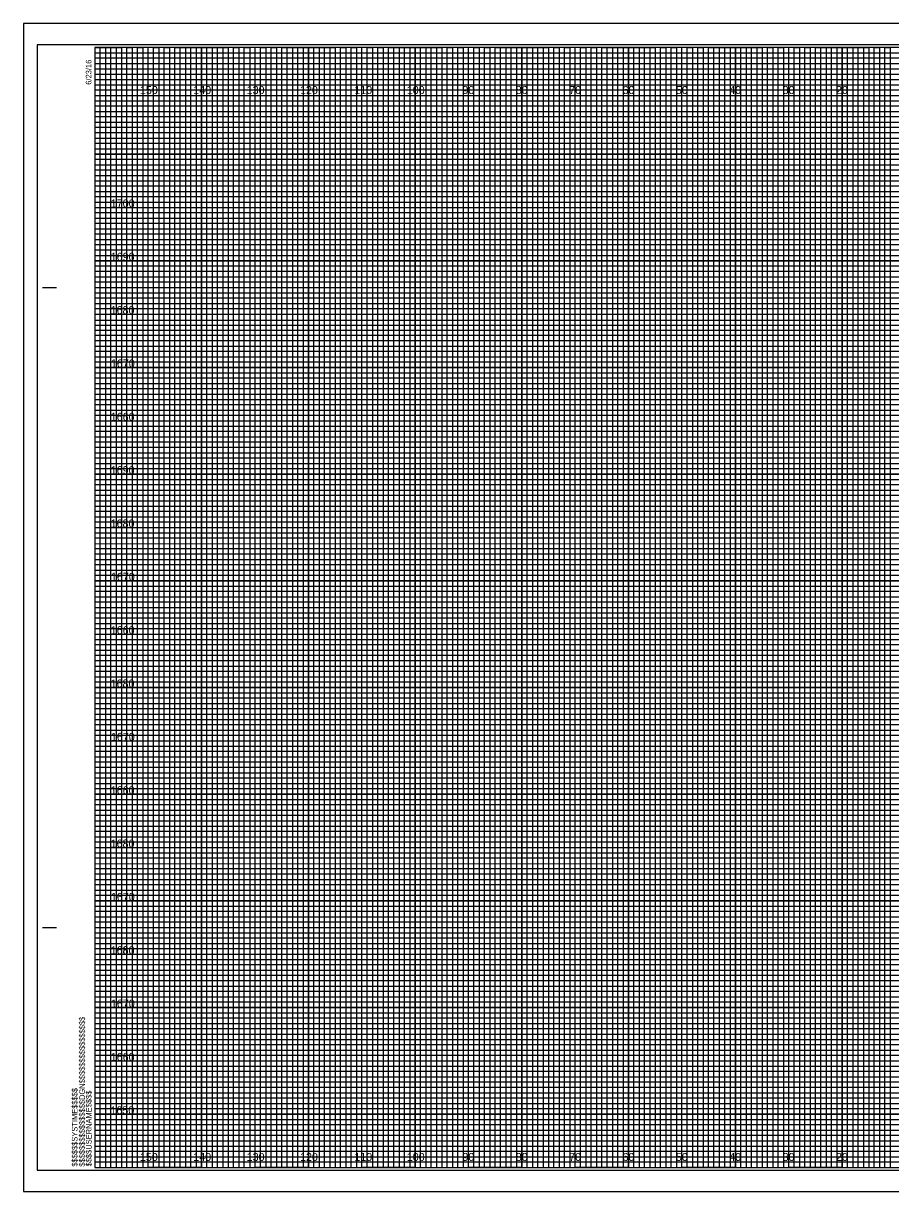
# Model space of a CAD drawing. Extents: x -13 to 323, y -5 to 434.
# Drawn here: x -13.4 to 149.1, y -4.5 to 214.5 of the extents above; entities that cross this region are included whole.
import ezdxf

# ---------------------------------------------------------------- set-up
doc = ezdxf.new("R2010")
doc.units = 0
for name, color, linetype in [('Prop Horizontal Alignment', 7, 'Continuous'), ('Raster_Level_0', 7, 'Continuous'), ('Sheet Cross Section CELL', 7, 'Continuous'), ('Sheet Cross Section Grid Major CELL', 7, 'Continuous'), ('Sheet Cross Section Grid Middle CELL', 7, 'Continuous'), ('Sheet Cross Section Grid Minor 1 CELL', 7, 'Continuous'), ('Sheet Cross Section Grid Minor 2 CELL', 7, 'Continuous'), ('Sheet Cutting Line CELL', 7, 'Continuous'), ('Sheet DOT Grid CELL', 7, 'Continuous'), ('Sheet Plot Border Inside CELL', 7, 'Continuous'), ('Sheet Plot Border Outside CELL', 7, 'Continuous')]:
    doc.layers.add(name, color=color, linetype=linetype)

msp = doc.modelspace()

# ---------------------------------------------------------------- linework, layer by layer
at = {"layer": 'Sheet Cross Section CELL'}
for p, q in [((-9.8, 165), (-7.3, 165)), ((-9.7, 165), (-7.2, 165)), ((-9.8, 45), (-7.3, 45)), ((-9.7, 45), (-7.2, 45)), ((0, 0), (0, 0)), ((0, 0), (0, 0)), ((0, 0), (0, 0)), ((0, 0), (0, 0)), ((0, 0), (0, 0)), ((0, 0), (0, 0)), ((0, 0), (0, 0))]:
    msp.add_line(p, q, dxfattribs=at)
msp.add_lwpolyline([(320, 210), (0, 210), (0, 0), (320, 0)], close=True, dxfattribs=at)
at = {"layer": 'Sheet Cross Section Grid Major CELL'}
for p, q in [((10, 210), (0, 210)), ((10, 0), (10, 210)), ((30, 210), (20, 210)), ((20, 210), (20, 0)), ((30, 0), (30, 210)), ((50, 210), (40, 210)), ((40, 210), (40, 0)), ((50, 0), (50, 210)), ((70, 210), (60, 210)), ((60, 210), (60, 0)), ((70, 0), (70, 210)), ((90, 210), (80, 210)), ((80, 210), (80, 0)), ((90, 0), (90, 210)), ((110, 210), (100, 210)), ((100, 210), (100, 0)), ((110, 0), (110, 210)), ((130, 210), (120, 210)), ((120, 210), (120, 0)), ((130, 0), (130, 210)), ((150, 210), (140, 210)), ((140, 210), (140, 0)), ((20, 0), (10, 0)), ((40, 0), (30, 0)), ((60, 0), (50, 0)), ((80, 0), (70, 0)), ((100, 0), (90, 0)), ((120, 0), (110, 0)), ((140, 0), (130, 0))]:
    msp.add_line(p, q, dxfattribs=at)
for points in [[(0, 200), (320, 200), (320, 190), (0, 190)], [(0, 180), (320, 180), (320, 170), (0, 170)], [(0, 160), (320, 160), (320, 150), (0, 150)], [(0, 140), (320, 140), (320, 130), (0, 130)], [(0, 120), (320, 120), (320, 110), (0, 110)], [(0, 100), (320, 100), (320, 90), (0, 90)], [(0, 80), (320, 80), (320, 70), (0, 70)], [(0, 60), (320, 60), (320, 50), (0, 50)], [(0, 40), (320, 40), (320, 30), (0, 30)], [(0, 20), (320, 20), (320, 10), (0, 10)]]:
    msp.add_lwpolyline(points, dxfattribs=at)
at = {"layer": 'Sheet Cross Section Grid Middle CELL'}
for points in [[(0, 210), (5, 210), (5, 0), (15, 0), (15, 210), (25, 210), (25, 0), (35, 0), (35, 210), (45, 210), (45, 0), (55, 0), (55, 210), (65, 210), (65, 0), (75, 0), (75, 210), (85, 210), (85, 0), (95, 0), (95, 210), (105, 210), (105, 0), (115, 0), (115, 210), (125, 210), (125, 0), (135, 0), (135, 210), (145, 210), (145, 0), (155, 0)], [(0, 205), (275, 205)], [(0, 185), (320, 185), (320, 195), (0, 195)], [(0, 165), (320, 165), (320, 175), (0, 175)], [(0, 145), (320, 145), (320, 155), (0, 155)], [(0, 125), (320, 125), (320, 135), (0, 135)], [(0, 105), (320, 105), (320, 115), (0, 115)], [(0, 85), (320, 85), (320, 95), (0, 95)], [(0, 65), (320, 65), (320, 75), (0, 75)], [(0, 45), (320, 45), (320, 55), (0, 55)], [(0, 25), (320, 25), (320, 35), (0, 35)], [(0, 5), (320, 5), (320, 15), (0, 15)]]:
    msp.add_lwpolyline(points, dxfattribs=at)
at = {"layer": 'Sheet Cross Section Grid Minor 1 CELL'}
for p, q in [((0, 209), (260, 209)), ((260, 207.98), (0, 207.98)), ((0, 207.98), (0, 207)), ((0, 207), (260, 207)), ((260, 205.89), (0, 205.89)), ((0, 205.89), (0, 204)), ((0, 204), (320, 204))]:
    msp.add_line(p, q, dxfattribs=at)
for points in [[(0, 203), (270, 203), (320, 203), (320, 202), (0, 202)], [(0, 201), (320, 201), (320, 199), (0, 199)], [(0, 198), (320, 198), (320, 197), (0, 196.98)], [(0, 196), (320, 196), (320, 194), (0, 194)], [(0, 193), (320, 193), (320, 192), (0, 192)], [(0, 191), (320, 191), (320, 189), (0, 189)], [(0, 188), (320, 188), (320, 187), (0, 187)], [(0, 186), (320, 186), (320, 184), (0, 184)], [(0, 183), (320, 183), (320, 182), (0, 182)], [(0, 181), (320, 181), (320, 179), (0, 179)], [(0, 178), (320, 178), (320, 177), (0, 177)], [(0, 176), (320, 176), (320, 173.95), (320, 173), (320, 172), (0, 172)], [(0, 174), (320, 174), (320, 173), (0, 173)], [(0, 171), (320, 171), (320, 169), (0, 169.03)], [(0, 169.03), (320, 169), (320, 168), (0, 168)], [(0, 167), (320, 167), (320, 166), (0, 166)], [(0, 164), (320, 164), (320, 163), (0, 163)], [(0, 162), (320, 162), (320, 161), (0, 161)], [(-0.07, 158.89), (320, 158.89), (320, 157.88), (-0.07, 157.88)], [(0, 157), (320, 157), (320, 156), (0, 156)], [(0, 154), (320, 154), (320, 153), (0, 153)], [(0, 152), (320, 152), (320, 151), (0, 151)], [(0, 149), (320, 149), (320, 148), (0, 148)], [(0, 147), (320, 147), (320, 146), (0, 146)], [(0, 144), (320, 144), (320, 143), (0, 143)], [(0, 142), (320, 142), (320, 141), (0, 141)], [(0, 139), (320, 139), (319.99, 137.98), (0, 138)], [(0, 137), (320, 137), (320, 136), (0, 136)], [(0, 134), (320, 134), (320, 133), (0, 133)], [(0, 132), (320, 132), (320, 131), (0, 131)], [(0, 129), (320, 129), (320, 128), (0, 128)], [(0, 127), (320, 127), (320, 126), (0, 126)], [(0, 124), (320, 124), (320, 123), (0, 123)], [(0, 122), (320, 122), (320, 121), (0, 121)], [(0, 119), (320, 119), (320, 118), (0, 118)], [(0, 116.99), (320.07, 116.91), (320, 116), (0, 116)], [(0, 114), (320, 114), (320, 113), (0, 113)], [(0, 112), (320, 112), (320, 111), (0, 111)], [(0, 109), (320, 109), (320, 108), (0, 108)], [(0, 107), (320, 107), (320, 106), (0, 106)], [(0, 104), (320, 104), (320, 103), (0, 103)], [(0, 102), (320, 102), (320, 101), (0, 101)], [(0, 99), (320, 99), (320, 98), (0, 98)], [(0, 97), (320, 97), (320, 96), (0, 96)], [(0, 94), (320, 94), (320, 93), (0, 93)], [(0, 92), (320, 92), (320, 91), (0, 91)], [(0, 89), (320, 89), (320, 88), (0, 88)], [(0, 87), (320, 87), (320, 86), (0, 86)], [(0, 84), (320, 84), (320, 83), (0, 83)], [(0, 82), (320, 82), (320, 81), (0, 81)], [(0, 79), (320, 79), (319.99, 77.98), (0, 78)], [(0, 77), (320, 77), (320, 76), (0, 76)], [(0, 74), (320, 74), (320, 73), (0, 73)], [(0, 72), (320, 72), (320, 71), (0, 71)], [(0, 69), (320, 69), (320, 68), (0, 68)], [(0, 67), (320, 67), (320, 66), (0, 66)], [(0, 64), (320, 64), (320, 63), (0, 63)], [(0, 62), (320, 62), (320, 61), (0, 61)], [(0, 59), (320, 59), (320, 58), (0, 58)], [(0, 56.99), (320.07, 56.91), (320, 56), (0, 56)], [(0, 54), (320, 54), (320, 53), (0, 53)], [(0, 52), (320, 52), (320, 51), (0, 51)], [(0, 49), (320, 49), (320, 48), (0, 48)], [(0, 47), (320, 47), (320, 46), (0, 46)], [(0, 44), (320, 44), (320, 43), (0, 43)], [(0, 42), (320, 42), (320, 41), (0, 41)], [(0, 39), (320, 39), (320, 38), (0, 38)], [(0, 37), (320, 37), (320, 36), (0, 36)], [(0, 34), (320, 34), (320, 33), (0, 33)], [(0, 32), (320, 32), (320, 31), (0, 31)], [(0, 29), (320, 29), (320, 28), (0, 28)], [(0, 27), (320, 27), (320, 26), (0, 26)], [(0, 24), (320, 24), (320, 23), (0, 23)], [(0, 22), (320, 22), (320, 21), (0, 21)], [(0, 19), (320, 19), (320, 18), (0, 18)], [(0, 17), (320, 17), (320, 16), (0, 16)], [(0, 14), (320, 14), (320, 13), (0, 13)], [(0, 12), (320, 12), (320, 11), (0, 11)], [(0, 9), (320, 9), (320, 8), (0, 8)], [(0, 7), (320, 7), (320, 6), (0, 6)], [(0, 4), (320, 4), (320, 3), (0, 3)], [(0, 2), (320, 2), (320, 1), (0, 1)]]:
    msp.add_lwpolyline(points, dxfattribs=at)
at = {"layer": 'Sheet Cross Section Grid Minor 2 CELL'}
for points in [[(0, 0), (1, 0), (1, 210), (2, 210), (2, 0)], [(2, 0), (3, 0), (3, 210), (4, 210), (4, 0)], [(5, 0), (6, 0), (6, 210), (7, 210), (7, 0)], [(7, 0), (8, 0), (8, 210), (9, 210), (9, 0)], [(10, 0), (11, 0), (11, 210), (12, 210), (12, 0)], [(12, 0), (13, 0), (13, 210), (14, 210), (14, 0)], [(15, 0), (16, 0), (16, 210), (17, 210), (17, 0)], [(17, 0), (18, 0), (18, 210), (19, 210), (19, 0)], [(20, 0), (21, 0), (21, 210), (22, 210), (22, 0)], [(22, 0), (23, 0), (23, 210), (24, 210), (24, 0)], [(25, 0), (26, 0), (26, 210), (27, 210), (27, 0)], [(27, 0), (28, 0), (28, 210), (29, 210), (29, 0)], [(30, 0), (31, 0), (31, 210), (32, 210), (32, 0)], [(32, 0), (33, 0), (33, 210), (34, 210), (34, 0)], [(35, 0), (36, 0), (36, 210), (37, 210), (37, 0)], [(37, 0), (38, 0), (38, 210), (39, 210), (39, 0)], [(40, 0), (41, 0), (41, 210), (42, 210), (42, 0)], [(42, 0), (43, 0), (43, 210), (44, 210), (44, 0)], [(45, 0), (46, 0), (46, 210), (47, 210), (47, 0)], [(47, 0), (48, 0), (48, 210), (49, 210), (49, 0)], [(50, 0), (51, 0), (51, 210), (52, 210), (52, 0)], [(52, 0), (53, 0), (53, 210), (54, 210), (54, 0)], [(55, 0), (56, 0), (56, 210), (57, 210), (57, 0)], [(57, 0), (58, 0), (58, 210), (59, 210), (59, 0)], [(60, 0), (61, 0), (61, 210), (62, 210), (62, 0)], [(62, 0), (63, 0), (63, 210), (64, 210), (64, 0)], [(65, 0), (66, 0), (66, 210), (67, 210), (67, 0)], [(67, 0), (68, 0), (68, 210), (69, 210), (69, 0)], [(70, 0), (71, 0), (71, 210), (72, 210), (72, 0)], [(72, 0), (73, 0), (73, 210), (74, 210), (74, 0)], [(75, 0), (76, 0), (76, 210), (77, 210), (77, 0)], [(77, 0), (78, 0), (78, 210), (79, 210), (79, 0)], [(80, 0), (81, 0), (81, 210), (82, 210), (82, 0)], [(82, 0), (83, 0), (83, 210), (84, 210), (84, 0)], [(85, 0), (86, 0), (86, 210), (87, 210), (87, 0)], [(87, 0), (88, 0), (88, 210), (89, 210), (89, 0)], [(90, 0), (91, 0), (91, 210), (92, 210), (92, 0)], [(92, 0), (93, 0), (93, 210), (94, 210), (94, 0)], [(95, 0), (96, 0), (96, 210), (97, 210), (97, 0)], [(97, 0), (98, 0), (98, 210), (99, 210), (99, 0)], [(100, 0), (101, 0), (101, 210), (102, 210), (102, 0)], [(102, 0), (103, 0), (103, 210), (104, 210), (104, 0)], [(105, 0), (106, 0), (106, 210), (107, 210), (107, 0)], [(107, 0), (108, 0), (108, 210), (109, 210), (109, 0)], [(110, 0), (111, 0), (111, 210), (112, 210), (112, 0)], [(112, 0), (113, 0), (113, 210), (114, 210), (114, 0)], [(115, 0), (116, 0), (116, 210), (117, 210), (117, 0)], [(117, 0), (118, 0), (118, 210), (119, 210), (119, 0)], [(120, 0), (121, 0), (121, 210), (122, 210), (122, 0)], [(122, 0), (123, 0), (123, 210), (124, 210), (124, 0)], [(125, 0), (126, 0), (126, 210), (127, 210), (127, 0)], [(127, 0), (128, 0), (128, 210), (129, 210), (129, 0)], [(130, 0), (131, 0), (131, 210), (132, 210), (132, 0)], [(132, 0), (133, 0), (133, 210), (134, 210), (134, 0)], [(135, 0), (136, 0), (136, 210), (137, 210), (137, 0)], [(137, 0), (138, 0), (138, 210), (139, 210), (139, 0)], [(140, 0), (141, 0), (141, 210), (142, 210), (142, 0)], [(142, 0), (143, 0), (143, 210), (144, 210), (144, 0)], [(145, 0), (146, 0), (146, 210), (147, 210), (147, 0)], [(147, 0), (148, 0), (148, 210), (149, 210), (149, 0)]]:
    msp.add_lwpolyline(points, dxfattribs=at)
at = {"layer": 'Sheet Cutting Line CELL'}
for p, q in [((323.3, 214.5), (-13.4, 214.5)), ((-13.4, 214.5), (-13.4, -4.5)), ((-13.4, -4.5), (323.3, -4.5))]:
    msp.add_line(p, q, dxfattribs=at)
at = {"layer": 'Sheet DOT Grid CELL'}
for p, q in [((10, 0), (10, 210)), ((20, 0), (20, 210)), ((30, 0), (30, 210)), ((40, 0), (40, 210)), ((50, 0), (50, 210)), ((60, 0), (60, 210)), ((70, 0), (70, 210)), ((80, 0), (80, 210)), ((90, 0), (90, 210)), ((100, 0), (100, 210)), ((110, 0), (110, 210)), ((120, 0), (120, 210)), ((130, 0), (130, 210)), ((140, 0), (140, 210)), ((0, 200), (320, 200)), ((0, 190), (320, 190)), ((0, 180), (320, 180)), ((0, 170), (320, 170)), ((0, 160), (320, 160)), ((0, 150), (320, 150)), ((0, 140), (320, 140)), ((0, 130), (320, 130)), ((0, 120), (320, 120)), ((0, 110), (320, 110)), ((0, 100), (320, 100)), ((0, 90), (320, 90)), ((0, 80), (320, 80)), ((0, 70), (320, 70)), ((0, 60), (320, 60)), ((0, 50), (320, 50)), ((0, 40), (320, 40)), ((0, 30), (320, 30)), ((0, 20), (320, 20)), ((0, 10), (320, 10))]:
    msp.add_line(p, q, dxfattribs=at)
at = {"layer": 'Sheet Plot Border Inside CELL'}
msp.add_lwpolyline([(-10.8, -0.5), (322.4, -0.5), (322.4, 210.5), (-10.8, 210.5)], close=True, dxfattribs=at)
at = {"layer": 'Sheet Plot Border Outside CELL'}
msp.add_lwpolyline([(-13.4, -4.5), (323.3, -4.5), (323.3, 214.5), (-13.4, 214.5)], close=True, dxfattribs=at)

# ---------------------------------------------------------------- texts
at = {"layer": 'Prop Horizontal Alignment'}
for s, p in [('1700', (2.98, 180)), ('1690', (2.97, 170)), ('1680', (2.95, 160)), ('1670', (3, 150)), ('1660', (2.97, 140)), ('1690', (2.97, 130)), ('1680', (2.95, 120)), ('1670', (3, 110)), ('1660', (2.97, 100)), ('1680', (2.95, 90)), ('1670', (3, 80)), ('1660', (2.97, 70)), ('1680', (2.95, 60)), ('1670', (3, 50)), ('1680', (2.95, 40)), ('1660', (2.97, 40)), ('1670', (3, 30)), ('1660', (2.97, 20)), ('1650', (2.92, 10))]:
    msp.add_text(s, height=1.5, dxfattribs=at).set_placement(p)
at = {"layer": 'Raster_Level_0'}
for s, p in [('150', (8.44, 201.25)), ('140', (18.44, 201.25)), ('130', (28.44, 201.25)), ('120', (38.44, 201.25)), ('110', (48.62, 201.25)), ('100', (58.44, 201.25)), ('90', (68.86, 201.25)), ('80', (78.86, 201.25)), ('70', (88.86, 201.25)), ('60', (98.86, 201.25)), ('50', (108.86, 201.25)), ('40', (118.86, 201.25)), ('30', (128.86, 201.25)), ('20', (138.86, 201.25)), ('150', (8.44, 1.25)), ('140', (18.44, 1.25)), ('130', (28.44, 1.25)), ('120', (38.44, 1.25)), ('110', (48.62, 1.25)), ('100', (58.44, 1.25)), ('90', (68.86, 1.25)), ('80', (78.86, 1.25)), ('70', (88.86, 1.25)), ('60', (98.86, 1.25)), ('50', (108.86, 1.25)), ('40', (118.86, 1.25)), ('30', (128.86, 1.25)), ('20', (138.86, 1.25))]:
    msp.add_text(s, height=1.5, dxfattribs=at).set_placement(p)
at = {"layer": 'Sheet Cross Section CELL'}
for s, p in [('6/23/16', (-0.65, 203)), ('$$$$$$$$$$$$$$$$DGN$$$$$$$$$$$$$$$$', (-1.88, 0.18)), ('$$$$$$SYSTIME$$$$$', (-3.26, 0.18)), ('$$$$USERNAME$$$$', (-0.62, 0.23))]:
    msp.add_text(s, height=1.05, rotation=90, dxfattribs=at).set_placement(p)

doc.saveas('drawing.dxf')
